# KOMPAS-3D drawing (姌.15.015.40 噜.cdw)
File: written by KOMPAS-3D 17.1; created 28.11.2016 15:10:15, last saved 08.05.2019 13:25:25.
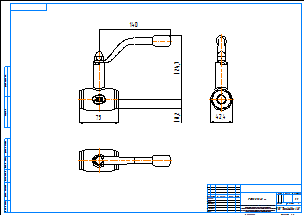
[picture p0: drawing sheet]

Sheet 1: A2, landscape

Title block, sheet 1: name: КШ.15.015.40 рр; material: Внимание! Данный продукт является объектом авторского права ООО «Торговый Дом АДЛ». / Запрещается изменение, копирование, распространение / (в том числе путем копирования на другие сайты и ресурсы в Интернете) / или любое иное использование информации и объектов без предварительного / согласия правообладателя (ООО «Торговый Дом АДЛ»).; sheets: 1; organisation: ООО "Торговый дом АДЛ"; sheet format: A2; stored path: C:\Users\tra\Desktop\2д чертежи\Шаровые краны БИВАЛ\КШ_Бивал_серия_14_15\KOMPAS_2D\КШ.15.015.40 рр.cdw

Views: Вид 1, Проекционный вид 2, Проекционный вид 3
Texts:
  Klimkovich
  ADL
Dimensions and other numbers on the sheet: 75; 140; 124,7; 18,2; 42,4; 1:1; 1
